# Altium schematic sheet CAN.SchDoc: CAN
size A4; DocumentNumber: MB1144; Revision: C-02; SheetNumber: 16; SheetTotal: 25; Project: STM32L476G-EVAL
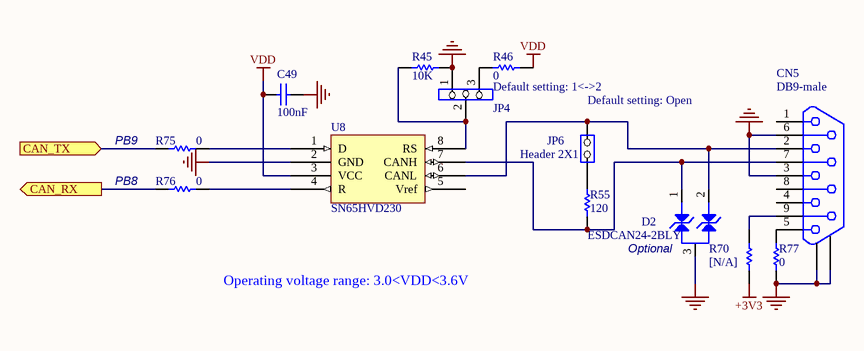
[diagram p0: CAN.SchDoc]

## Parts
C49  100nF  [0402C]
CN5  DB9-male  [DB9/M]
D2  ESDCAN24-2BLY  [SOT23-213]
JP4  Header 3X1  [SIP3]  (value not drawn)
JP6  Header 2X1  [SIP2]
R45  10K  [0402R]
R46  0  [0603R]
R55  120  [0402R]
R70  [N/A]  [0603R]
R75  0  [0603R]
R76  0  [0603R]
R77  0  [0603R]
U8  SN65HVD230  [SOIC8_1R27_4R9X6]

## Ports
CAN_RX (out), CAN_TX (in)

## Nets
+3V3: R70.1
GND: C49.1 CN5.3 CN5.6 CN5.10 CN5.11 D2.3 JP4.1 R45.2 R77.1 U8.2(GND)
VDD: C49.2 R46.2 U8.3(VCC)
CAN_RX: R76.1 ; port CAN_RX
CAN_TX: R75.2 ; port CAN_TX
NetCN5_2: CN5.2 D2.2 JP6.2(NO) U8.6(CANL)
NetCN5_5: CN5.5 R77.2
NetCN5_7: CN5.7 D2.1 R55.1 U8.7(CANH)
NetCN5_9: CN5.9 R70.2
NetJP4_2: JP4.2 R45.1 U8.8(RS)
NetJP4_3: JP4.3 R46.1
NetJP6_1: JP6.1(COMMON) R55.2
NetR75_1: R75.1 U8.1(D)
NetR76_2: R76.2 U8.4(R)

Not connected (* = marked no-connect by the designer): CN5 1 4 8; U8 5(Vref)

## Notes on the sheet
- Default setting: 1<->2
- (near JP6) Default setting: Open
- PB9
- PB8
- (near D2) Optional
- Operating voltage range: 3.0<VDD<3.6V

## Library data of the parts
C49 = CAP: Capacitor; Ordered by: Subcon; ECCN_US/EU: NA
CN5 = DB9: Ordered by: Subcon; Comments: DB9 CAN; ECCN_US/EU: NA
D2 = ESDCAN24-2BLY: Ordered by: ST; ECCN_US/EU: EAR99/NEC; Ref St: 9179002
JP4 = Jumper3: Ordered by: Subcon; ECCN_US/EU: NA
JP6 = JP2: Ordered by: Subcon; ECCN_US/EU: NA
R45 R46 R55 R77 = res1: Resistor; Value: 1K; Ordered by: Subcon; ECCN_US/EU: NA
R70 = res1: Resistor; Value: 1K; Ordered by: Subcon; ECCN_US/EU: NA; Fitted: NO
R75 R76 = Res1: Resistor; Value: 1K; Ordered by: Subcon; ECCN_US/EU: NA
U8 = SN65HVD230D: Manuf_1: TI; Ordered by: Subcon; ECCN_US/EU: EAR99/NEC; Comments: QSPI memory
